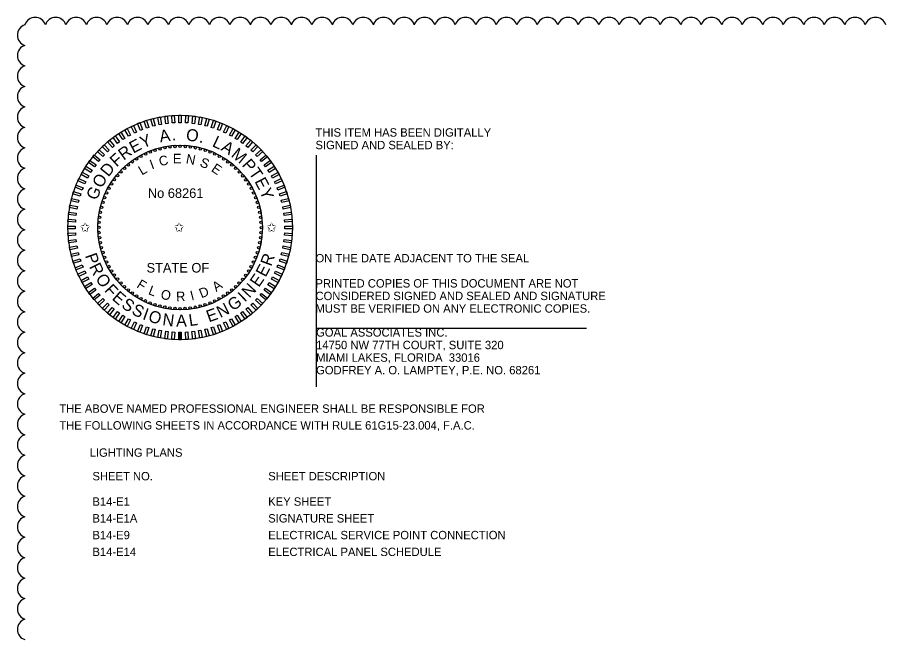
# Model space of a CAD drawing. Extents: x -811.3 to -795.2, y -2199.5 to -2188.9.
# Drawn here: x -810.85 to -803.6, y -2194.13 to -2188.94 of the extents above; entities that cross this region are included whole.
import ezdxf

# ---------------------------------------------------------------- set-up
doc = ezdxf.new("R2010")
doc.units = 0
for name, color, linetype in [('PlotBorder_dp', 7, 'Continuous'), ('ScratchEle_dp', 7, 'Continuous'), ('SheetBorder_dp', 7, 'Continuous'), ('SheetLines_dp', 7, 'Continuous'), ('TextMinor', 7, 'Continuous'), ('TextMisc', 7, 'Continuous')]:
    doc.layers.add(name, color=color, linetype=linetype)

msp = doc.modelspace()

# ---------------------------------------------------------------- linework, layer by layer
at = {"layer": 'PlotBorder_dp'}
for p, q in [((-809.5001, -2191.6301), (-809.5003, -2191.5676)), ((-809.4901, -2191.6301), (-809.4903, -2191.5676)), ((-809.4801, -2191.6301), (-809.4803, -2191.5676))]:
    msp.add_line(p, q, dxfattribs=at)
for points in [[(-809.7508, -2189.8572), (-809.77, -2189.8635), (-809.7893, -2189.8041), (-809.7701, -2189.7979)], [(-809.6979, -2189.8425), (-809.7174, -2189.8475), (-809.7329, -2189.7871), (-809.7134, -2189.782)], [(-809.6441, -2189.8312), (-809.6639, -2189.8349), (-809.6756, -2189.7736), (-809.6558, -2189.7698)], [(-809.5897, -2189.8232), (-809.6097, -2189.8257), (-809.6175, -2189.7638), (-809.5975, -2189.7612)], [(-809.5349, -2189.8187), (-809.555, -2189.8199), (-809.559, -2189.7576), (-809.5388, -2189.7563)], [(-809.4799, -2189.8176), (-809.5001, -2189.8176), (-809.5001, -2189.7551), (-809.4799, -2189.7551)], [(-809.425, -2189.8199), (-809.4452, -2189.8187), (-809.4412, -2189.7563), (-809.4211, -2189.7576)], [(-809.3703, -2189.8257), (-809.3904, -2189.8232), (-809.3825, -2189.7613), (-809.3625, -2189.7638)], [(-809.3162, -2189.835), (-809.336, -2189.8312), (-809.3243, -2189.7699), (-809.3045, -2189.7736)], [(-809.2626, -2189.8476), (-809.2822, -2189.8426), (-809.2667, -2189.7821), (-809.2471, -2189.7871)], [(-809.21, -2189.8635), (-809.2292, -2189.8573), (-809.2099, -2189.7979), (-809.1907, -2189.8042)], [(-809.9027, -2189.9209), (-809.9204, -2189.9306), (-809.9505, -2189.8759), (-809.9328, -2189.8662)], [(-809.8535, -2189.8965), (-809.8717, -2189.9051), (-809.8983, -2189.8486), (-809.8801, -2189.84)], [(-809.8028, -2189.8753), (-809.8215, -2189.8827), (-809.8445, -2189.8246), (-809.8258, -2189.8172)], [(-809.1585, -2189.8828), (-809.1773, -2189.8753), (-809.1543, -2189.8173), (-809.1355, -2189.8247)], [(-809.1083, -2189.9052), (-809.1266, -2189.8966), (-809.1, -2189.8401), (-809.0817, -2189.8487)], [(-809.0596, -2189.9307), (-809.0773, -2189.921), (-809.0473, -2189.8663), (-809.0296, -2189.876)], [(-809.9962, -2189.9787), (-810.0125, -2189.9906), (-810.0492, -2189.94), (-810.0329, -2189.9282)], [(-809.9504, -2189.9483), (-809.9674, -2189.9591), (-810.0009, -2189.9064), (-809.9838, -2189.8956)], [(-809.0127, -2189.9592), (-809.0297, -2189.9484), (-808.9962, -2189.8957), (-808.9792, -2189.9065)], [(-808.9676, -2189.9907), (-808.9839, -2189.9788), (-808.9472, -2189.9283), (-808.9308, -2189.9402)], [(-810.0817, -2190.0478), (-810.0964, -2190.0616), (-810.1392, -2190.0161), (-810.1244, -2190.0022)], [(-810.04, -2190.0119), (-810.0556, -2190.0247), (-810.0954, -2189.9766), (-810.0798, -2189.9638)], [(-808.9245, -2190.0249), (-808.9401, -2190.012), (-808.9003, -2189.9639), (-808.8847, -2189.9768)], [(-808.8837, -2190.0617), (-808.8984, -2190.0479), (-808.8557, -2190.0024), (-808.841, -2190.0162)], [(-810.1579, -2190.127), (-810.1707, -2190.1425), (-810.2188, -2190.1027), (-810.206, -2190.0872)], [(-810.121, -2190.0862), (-810.1348, -2190.1009), (-810.1804, -2190.0581), (-810.1665, -2190.0434)], [(-808.8453, -2190.101), (-808.8591, -2190.0863), (-808.8136, -2190.0436), (-808.7998, -2190.0583)], [(-808.8094, -2190.1427), (-808.8223, -2190.1271), (-808.7742, -2190.0873), (-808.7613, -2190.1029)], [(-810.192, -2190.17), (-810.2039, -2190.1864), (-810.2544, -2190.1497), (-810.2426, -2190.1333)], [(-808.7762, -2190.1865), (-808.7881, -2190.1702), (-808.7376, -2190.1335), (-808.7257, -2190.1498)], [(-810.252, -2190.2621), (-810.2617, -2190.2798), (-810.3164, -2190.2497), (-810.3067, -2190.232)], [(-810.2235, -2190.2151), (-810.2343, -2190.2322), (-810.287, -2190.1987), (-810.2762, -2190.1817)], [(-808.7459, -2190.2323), (-808.7567, -2190.2153), (-808.7039, -2190.1818), (-808.6931, -2190.1989)], [(-808.7184, -2190.28), (-808.7281, -2190.2623), (-808.6734, -2190.2322), (-808.6637, -2190.2499)], [(-810.2775, -2190.3108), (-810.2861, -2190.3291), (-810.3426, -2190.3025), (-810.334, -2190.2842)], [(-808.694, -2190.3292), (-808.7026, -2190.311), (-808.6461, -2190.2844), (-808.6375, -2190.3027)], [(-810.3, -2190.361), (-810.3074, -2190.3798), (-810.3654, -2190.3568), (-810.358, -2190.338)], [(-808.6728, -2190.3799), (-808.6802, -2190.3612), (-808.6222, -2190.3382), (-808.6147, -2190.357)], [(-810.3351, -2190.4651), (-810.3401, -2190.4847), (-810.4006, -2190.4691), (-810.3956, -2190.4496)], [(-810.3192, -2190.4125), (-810.3254, -2190.4317), (-810.3848, -2190.4124), (-810.3786, -2190.3932)], [(-808.6548, -2190.4319), (-808.661, -2190.4127), (-808.6016, -2190.3934), (-808.5954, -2190.4126)], [(-808.64, -2190.4849), (-808.6451, -2190.4653), (-808.5846, -2190.4498), (-808.5796, -2190.4693)], [(-810.3477, -2190.5186), (-810.3515, -2190.5385), (-810.4129, -2190.5268), (-810.4091, -2190.5069)], [(-808.6287, -2190.5386), (-808.6325, -2190.5188), (-808.5711, -2190.5071), (-808.5673, -2190.5269)], [(-810.357, -2190.5728), (-810.3595, -2190.5928), (-810.4215, -2190.585), (-810.4189, -2190.565)], [(-808.6207, -2190.593), (-808.6232, -2190.573), (-808.5613, -2190.5652), (-808.5588, -2190.5852)], [(-810.3628, -2190.6275), (-810.3641, -2190.6476), (-810.4264, -2190.6437), (-810.4251, -2190.6236)], [(-808.6162, -2190.6478), (-808.6174, -2190.6277), (-808.5551, -2190.6238), (-808.5539, -2190.6439)], [(-810.3652, -2190.6824), (-810.3652, -2190.7026), (-810.4276, -2190.7026), (-810.4276, -2190.6824)], [(-810.3641, -2190.7374), (-810.3628, -2190.7575), (-810.4251, -2190.7614), (-810.4264, -2190.7413)], [(-808.6175, -2190.7577), (-808.6162, -2190.7376), (-808.5539, -2190.7415), (-808.5551, -2190.7616)], [(-808.6151, -2190.7028), (-808.6151, -2190.6826), (-808.5527, -2190.6826), (-808.5527, -2190.7028)], [(-810.3595, -2190.7922), (-810.357, -2190.8122), (-810.4189, -2190.82), (-810.4215, -2190.8)], [(-808.6233, -2190.8124), (-808.6207, -2190.7923), (-808.5588, -2190.8002), (-808.5613, -2190.8202)], [(-810.3516, -2190.8466), (-810.3478, -2190.8664), (-810.4091, -2190.8781), (-810.4129, -2190.8583)], [(-808.6325, -2190.8666), (-808.6287, -2190.8467), (-808.5674, -2190.8584), (-808.5712, -2190.8783)], [(-810.3402, -2190.9003), (-810.3352, -2190.9199), (-810.3957, -2190.9354), (-810.4007, -2190.9159)], [(-810.3255, -2190.9533), (-810.3192, -2190.9725), (-810.3786, -2190.9918), (-810.3849, -2190.9726)], [(-808.6611, -2190.9727), (-808.6548, -2190.9535), (-808.5954, -2190.9728), (-808.6017, -2190.992)], [(-808.6451, -2190.9201), (-808.6401, -2190.9005), (-808.5796, -2190.916), (-808.5846, -2190.9356)], [(-810.3075, -2191.0052), (-810.3, -2191.024), (-810.3581, -2191.047), (-810.3655, -2191.0282)], [(-808.6803, -2191.0242), (-808.6729, -2191.0054), (-808.6148, -2191.0284), (-808.6222, -2191.0472)], [(-810.2862, -2191.0559), (-810.2776, -2191.0742), (-810.3341, -2191.1008), (-810.3427, -2191.0825)], [(-810.2618, -2191.1052), (-810.2521, -2191.1229), (-810.3068, -2191.153), (-810.3165, -2191.1353)], [(-808.7282, -2191.1231), (-808.7185, -2191.1054), (-808.6638, -2191.1355), (-808.6735, -2191.1532)], [(-808.7027, -2191.0744), (-808.6941, -2191.0561), (-808.6376, -2191.0827), (-808.6462, -2191.101)], [(-810.2344, -2191.1529), (-810.2236, -2191.1699), (-810.2763, -2191.2034), (-810.2871, -2191.1863)], [(-808.7568, -2191.1701), (-808.746, -2191.153), (-808.6932, -2191.1865), (-808.704, -2191.2035)], [(-810.204, -2191.1987), (-810.1922, -2191.215), (-810.2427, -2191.2517), (-810.2545, -2191.2354)], [(-810.1708, -2191.2425), (-810.158, -2191.2581), (-810.2061, -2191.2979), (-810.2189, -2191.2823)], [(-808.8224, -2191.2582), (-808.8095, -2191.2427), (-808.7614, -2191.2825), (-808.7743, -2191.298)], [(-808.7882, -2191.2152), (-808.7763, -2191.1988), (-808.7258, -2191.2355), (-808.7377, -2191.2519)], [(-810.135, -2191.2842), (-810.1211, -2191.2989), (-810.1667, -2191.3416), (-810.1805, -2191.3269)], [(-810.0965, -2191.3235), (-810.0818, -2191.3373), (-810.1246, -2191.3828), (-810.1393, -2191.369)], [(-808.8985, -2191.3374), (-808.8838, -2191.3236), (-808.8411, -2191.3691), (-808.8558, -2191.383)], [(-808.8592, -2191.299), (-808.8454, -2191.2843), (-808.7999, -2191.327), (-808.8137, -2191.3418)], [(-810.0557, -2191.3603), (-810.0402, -2191.3732), (-810.08, -2191.4213), (-810.0955, -2191.4084)], [(-810.0127, -2191.3945), (-809.9964, -2191.4064), (-810.0331, -2191.4569), (-810.0494, -2191.445)], [(-808.984, -2191.4065), (-808.9677, -2191.3946), (-808.931, -2191.4451), (-808.9473, -2191.457)], [(-808.9402, -2191.3733), (-808.9247, -2191.3604), (-808.8848, -2191.4086), (-808.9004, -2191.4214)], [(-809.9676, -2191.426), (-809.9505, -2191.4368), (-809.984, -2191.4895), (-810.001, -2191.4787)], [(-809.9206, -2191.4545), (-809.9029, -2191.4642), (-809.933, -2191.5189), (-809.9507, -2191.5092)], [(-809.0775, -2191.4643), (-809.0598, -2191.4546), (-809.0297, -2191.5093), (-809.0474, -2191.519)], [(-809.0299, -2191.4369), (-809.0128, -2191.4261), (-808.9794, -2191.4788), (-808.9964, -2191.4896)], [(-809.8719, -2191.48), (-809.8536, -2191.4886), (-809.8802, -2191.5451), (-809.8985, -2191.5365)], [(-809.8217, -2191.5024), (-809.8029, -2191.5099), (-809.8259, -2191.5679), (-809.8447, -2191.5605)], [(-809.7702, -2191.5217), (-809.751, -2191.5279), (-809.7703, -2191.5873), (-809.7895, -2191.581)], [(-809.7176, -2191.5376), (-809.698, -2191.5426), (-809.7136, -2191.6031), (-809.7331, -2191.5981)], [(-809.2824, -2191.5427), (-809.2628, -2191.5376), (-809.2473, -2191.5981), (-809.2668, -2191.6031)], [(-809.2294, -2191.5279), (-809.2102, -2191.5217), (-809.1909, -2191.5811), (-809.2101, -2191.5873)], [(-809.1775, -2191.5099), (-809.1587, -2191.5025), (-809.1357, -2191.5606), (-809.1545, -2191.568)], [(-809.1268, -2191.4887), (-809.1085, -2191.4801), (-809.0819, -2191.5366), (-809.1002, -2191.5452)], [(-809.6641, -2191.5502), (-809.6443, -2191.554), (-809.656, -2191.6153), (-809.6758, -2191.6116)], [(-809.6099, -2191.5594), (-809.5899, -2191.562), (-809.5977, -2191.6239), (-809.6177, -2191.6214)], [(-809.5552, -2191.5653), (-809.5351, -2191.5665), (-809.539, -2191.6288), (-809.5592, -2191.6276)], [(-809.5003, -2191.5676), (-809.4801, -2191.5676), (-809.4801, -2191.6301), (-809.5003, -2191.6301)], [(-809.4453, -2191.5665), (-809.4252, -2191.5653), (-809.4213, -2191.6276), (-809.4414, -2191.6289)], [(-809.3906, -2191.562), (-809.3705, -2191.5595), (-809.3627, -2191.6214), (-809.3827, -2191.624)], [(-809.3362, -2191.554), (-809.3163, -2191.5503), (-809.3046, -2191.6116), (-809.3245, -2191.6154)]]:
    msp.add_lwpolyline(points, close=True, dxfattribs=at)
for centre in [(-809.6165, -2190.027), (-809.5745, -2190.0204), (-809.5321, -2190.0164), (-809.4896, -2190.0151), (-809.447, -2190.0165), (-809.4047, -2190.0205), (-809.3626, -2190.0272), (-809.816, -2190.0987), (-809.7781, -2190.0794), (-809.739, -2190.0625), (-809.6989, -2190.0481), (-809.6581, -2190.0363), (-809.3211, -2190.0366), (-809.2802, -2190.0485), (-809.2402, -2190.0629), (-809.2012, -2190.0798), (-809.1633, -2190.0992), (-809.9215, -2190.1702), (-809.8879, -2190.1442), (-809.8527, -2190.1203), (-809.1266, -2190.1209), (-809.0915, -2190.1448), (-809.0579, -2190.171), (-809.9836, -2190.2284), (-809.9535, -2190.1984), (-809.026, -2190.1991), (-808.9959, -2190.2292), (-810.0379, -2190.2939), (-810.0118, -2190.2603), (-808.9678, -2190.2612), (-808.9417, -2190.2948), (-810.0835, -2190.3657), (-810.0618, -2190.3291), (-808.9178, -2190.3301), (-808.8962, -2190.3667), (-810.1198, -2190.4427), (-810.1029, -2190.4036), (-808.8769, -2190.4047), (-808.86, -2190.4437), (-810.1462, -2190.5236), (-810.1343, -2190.4827), (-808.8456, -2190.4838), (-808.8338, -2190.5247), (-810.1622, -2190.6071), (-810.1555, -2190.5651), (-808.8245, -2190.5662), (-808.8179, -2190.6082), (-810.1662, -2190.6495), (-808.814, -2190.6506), (-810.1676, -2190.692), (-810.1663, -2190.7346), (-808.814, -2190.7357), (-808.8127, -2190.6932), (-810.1623, -2190.7769), (-810.1557, -2190.819), (-808.8248, -2190.8201), (-808.8181, -2190.7781), (-810.1464, -2190.8605), (-810.1346, -2190.9014), (-808.846, -2190.9025), (-808.8341, -2190.8616), (-810.1202, -2190.9415), (-808.8604, -2190.9425), (-810.1034, -2190.9805), (-810.0841, -2191.0185), (-808.8967, -2191.0195), (-808.8774, -2190.9816), (-810.0624, -2191.0551), (-810.0385, -2191.0903), (-808.9424, -2191.0913), (-808.9184, -2191.0561), (-810.0125, -2191.124), (-809.9844, -2191.1559), (-809.9543, -2191.1861), (-809.0268, -2191.1868), (-808.9967, -2191.1568), (-808.9685, -2191.1249), (-809.9224, -2191.2142), (-809.8888, -2191.2403), (-809.8536, -2191.2643), (-809.1276, -2191.2649), (-809.0924, -2191.241), (-809.0587, -2191.215), (-809.817, -2191.286), (-809.7791, -2191.3053), (-809.74, -2191.3223), (-809.7, -2191.3367), (-809.2813, -2191.3371), (-809.2413, -2191.3227), (-809.2022, -2191.3058), (-809.1642, -2191.2865), (-809.6591, -2191.3486), (-809.6176, -2191.358), (-809.5756, -2191.3647), (-809.5332, -2191.3687), (-809.4901, -2191.3701), (-809.4481, -2191.3688), (-809.4058, -2191.3648), (-809.3637, -2191.3582), (-809.3222, -2191.3489)]:
    msp.add_circle(centre, 0.01, dxfattribs=at)
at = {"layer": 'ScratchEle_dp'}
for centre, start, end in [((-810.7588, -2189.0862), 107.5, 252.5), ((-810.7002, -2189.0276), 17.5, 162.5), ((-810.5291, -2189.0276), 17.5, 162.5), ((-810.358, -2189.0276), 17.5, 162.5), ((-810.1868, -2189.0276), 17.5, 162.5), ((-810.0157, -2189.0276), 17.5, 162.5), ((-809.8446, -2189.0276), 17.5, 162.5), ((-809.6735, -2189.0276), 17.5, 162.5), ((-809.5024, -2189.0276), 17.5, 162.5), ((-809.3312, -2189.0276), 17.5, 162.5), ((-809.1601, -2189.0276), 17.5, 162.5), ((-808.989, -2189.0276), 17.5, 162.5), ((-808.8179, -2189.0276), 17.5, 162.5), ((-808.6467, -2189.0276), 17.5, 162.5), ((-808.4756, -2189.0276), 17.5, 162.5), ((-808.3045, -2189.0276), 17.5, 162.5), ((-808.1334, -2189.0276), 17.5, 162.5), ((-807.9622, -2189.0276), 17.5, 162.5), ((-807.7911, -2189.0276), 17.5, 162.5), ((-807.62, -2189.0276), 17.5, 162.5), ((-807.4489, -2189.0276), 17.5, 162.5), ((-807.2778, -2189.0276), 17.5, 162.5), ((-807.1066, -2189.0276), 17.5, 162.5), ((-806.9355, -2189.0276), 17.5, 162.5), ((-806.7644, -2189.0276), 17.5, 162.5), ((-806.5933, -2189.0276), 17.5, 162.5), ((-806.4221, -2189.0276), 17.5, 162.5), ((-806.251, -2189.0276), 17.5, 162.5), ((-806.0799, -2189.0276), 17.5, 162.5), ((-805.9088, -2189.0276), 17.5, 162.5), ((-805.7377, -2189.0276), 17.5, 162.5), ((-805.5665, -2189.0276), 17.5, 162.5), ((-805.3954, -2189.0276), 17.5, 162.5), ((-805.2243, -2189.0276), 17.5, 162.5), ((-805.0532, -2189.0276), 17.5, 162.5), ((-804.882, -2189.0276), 17.5, 162.5), ((-804.7109, -2189.0276), 17.5, 162.5), ((-804.5398, -2189.0276), 17.5, 162.5), ((-804.3687, -2189.0276), 17.5, 162.5), ((-804.1976, -2189.0276), 17.5, 162.5), ((-804.0264, -2189.0276), 17.5, 162.5), ((-803.8553, -2189.0276), 17.5, 162.5), ((-803.6842, -2189.0276), 17.5, 162.5), ((-810.7588, -2189.2573), 107.5, 252.5), ((-810.7588, -2189.4284), 107.5, 252.5), ((-810.7588, -2189.5996), 107.5, 252.5), ((-810.7588, -2189.7707), 107.5, 252.5), ((-810.7588, -2189.9418), 107.5, 252.5), ((-810.7588, -2190.1129), 107.5, 252.5), ((-810.7588, -2190.2841), 107.5, 252.5), ((-810.7588, -2190.4552), 107.5, 252.5), ((-810.7588, -2190.6263), 107.5, 252.5), ((-810.7588, -2190.7974), 107.5, 252.5), ((-810.7588, -2190.9685), 107.5, 252.5), ((-810.7588, -2191.1397), 107.5, 252.5), ((-810.7588, -2191.3108), 107.5, 252.5), ((-810.7588, -2191.4819), 107.5, 252.5), ((-810.7588, -2191.653), 107.5, 252.5), ((-810.7588, -2191.8242), 107.5, 252.5), ((-810.7588, -2191.9953), 107.5, 252.5), ((-810.7588, -2192.1664), 107.5, 252.5), ((-810.7588, -2192.3375), 107.5, 252.5), ((-810.7588, -2192.5087), 107.5, 252.5), ((-810.7588, -2192.6798), 107.5, 252.5), ((-810.7588, -2192.8509), 107.5, 252.5), ((-810.7588, -2193.022), 107.5, 252.5), ((-810.7588, -2193.1931), 107.5, 252.5), ((-810.7588, -2193.3643), 107.5, 252.5), ((-810.7588, -2193.5354), 107.5, 252.5), ((-810.7588, -2193.7065), 107.5, 252.5), ((-810.7588, -2193.8776), 107.5, 252.5), ((-810.7588, -2194.0488), 107.5, 252.5)]:
    msp.add_arc(centre, 0.0897, start, end, dxfattribs=at)
at = {"layer": 'SheetLines_dp'}
for radius in [0.9375, 0.6875]:
    msp.add_circle((-809.4901, -2190.6926), radius, dxfattribs=at)
at = {"layer": 'TextMisc'}
for p, q in [((-808.3546, -2190.0892), (-808.3546, -2192.0239)), ((-808.3546, -2191.5339), (-806.0979, -2191.5339))]:
    msp.add_line(p, q, dxfattribs=at)

# ---------------------------------------------------------------- texts
at = {"layer": 'PlotBorder_dp'}
for s, height, rotation, p in [('A', 0.1, 8.80884, (-809.6551, -2189.982)), ('O', 0.1, 352.18771, (-809.4449, -2189.9645)), ('E', 0.1, 28.10553, (-809.8806, -2190.0764)), ('Y', 0.1, 21.06329, (-809.8021, -2190.0332)), ('.', 0.1, 1.04184, (-809.5575, -2189.9662)), ('L', 0.1, 334.67271, (-809.2279, -2190.0118)), ('R', 0.1, 35.92688, (-809.9609, -2190.1353)), ('.', 0.1, 343.52684, (-809.3358, -2189.9796)), ('A', 0.1, 328.40959, (-809.1552, -2190.0445)), ('F', 0.1, 42.37723, (-810.0205, -2190.1917)), ('C', 0.08, 12.20255, (-809.6579, -2190.181)), ('E', 0.08, 0.41861, (-809.5498, -2190.1575)), ('N', 0.08, 349.29143, (-809.4455, -2190.1561)), ('M', 0.1, 320.6426, (-809.0707, -2190.0957)), ('D', 0.1, 50.8569, (-810.0886, -2190.2754)), ('I', 0.08, 20.01168, (-809.7258, -2190.2085)), ('S', 0.08, 337.02207, (-809.3325, -2190.1778)), ('E', 0.08, 325.86633, (-809.2358, -2190.218)), ('P', 0.1, 311.19658, (-808.9784, -2190.1727)), ('L', 0.08, 30.40215, (-809.8093, -2190.259)), ('T', 0.1, 304.45632, (-808.9209, -2190.2363)), ('O', 0.1, 59.51777, (-810.1446, -2190.3702)), ('E', 0.1, 297.63152, (-808.8707, -2190.3072)), ('G', 0.1, 68.0518, (-810.1851, -2190.4709)), ('Y', 0.1, 290.58928, (-808.8281, -2190.386)), ('P', 0.1, 289.40551, (-810.2848, -2190.9272)), ('R', 0.1, 69.5134, (-808.7299, -2191.0223)), ('R', 0.1, 296.14576, (-810.2518, -2191.0188)), ('E', 0.1, 62.47116, (-808.7761, -2191.113)), ('O', 0.1, 303.96711, (-810.2003, -2191.1194)), ('E', 0.1, 55.42892, (-808.833, -2191.1974)), ('F', 0.1, 312.62798, (-810.1279, -2191.2215)), ('F', 0.08, 328.72408, (-809.8582, -2191.1892)), ('L', 0.08, 339.29159, (-809.7609, -2191.2483)), ('A', 0.08, 34.49917, (-809.1883, -2191.232)), ('N', 0.1, 47.17876, (-808.9123, -2191.2864)), ('E', 0.1, 319.07833, (-810.0645, -2191.2898)), ('O', 0.08, 349.68206, (-809.6562, -2191.288)), ('R', 0.08, 2.33977, (-809.5217, -2191.3099)), ('I', 0.08, 14.20366, (-809.3941, -2191.3032)), ('D', 0.08, 22.01279, (-809.312, -2191.2845)), ('I', 0.1, 43.64556, (-808.9499, -2191.3209)), ('S', 0.1, 326.12056, (-809.9869, -2191.3557)), ('N', 0.1, 26.86136, (-809.1544, -2191.4501)), ('G', 0.1, 35.11153, (-809.0492, -2191.3941)), ('S', 0.1, 333.193, (-809.9015, -2191.4119)), ('I', 0.1, 340.26543, (-809.8098, -2191.457)), ('O', 0.1, 343.79863, (-809.7621, -2191.4753)), ('E', 0.1, 19.81912, (-809.2498, -2191.4856)), ('N', 0.1, 352.45949, (-809.6411, -2191.5073)), ('A', 0.1, 0.70966, (-809.5227, -2191.5206)), ('L', 0.1, 8.47665, (-809.4105, -2191.5174))]:
    msp.add_text(s, height=height, rotation=rotation, dxfattribs=at).set_placement(p)
for s, p in [('No 68261', (-809.7591, -2190.4454)), ('✩', (-810.3251, -2190.7305)), ('✩', (-809.5404, -2190.7305)), ('✩', (-808.7685, -2190.7305)), ('STATE OF', (-809.7698, -2191.0688))]:
    msp.add_text(s, height=0.08, dxfattribs=at).set_placement(p)
at = {"layer": 'SheetBorder_dp'}
for s, p in [('THIS ITEM HAS BEEN DIGITALLY', (-808.3596, -2189.934)), ('SIGNED AND SEALED BY:', (-808.3596, -2190.039)), ('ON THE DATE ADJACENT TO THE SEAL', (-808.3596, -2190.984)), ('PRINTED COPIES OF THIS DOCUMENT ARE NOT ', (-808.3596, -2191.194)), ('CONSIDERED SIGNED AND SEALED AND SIGNATURE ', (-808.3596, -2191.299)), ('MUST BE VERIFIED ON ANY ELECTRONIC COPIES.', (-808.3596, -2191.404)), ('GOAL ASSOCIATES INC.', (-808.3546, -2191.6039)), ('14750 NW 77TH COURT, SUITE 320', (-808.3546, -2191.7089)), ('MIAMI LAKES, FLORIDA  33016', (-808.3546, -2191.8139)), ('GODFREY A. O. LAMPTEY, P.E. NO. 68261', (-808.3546, -2191.9189)), ('THE ABOVE NAMED PROFESSIONAL ENGINEER SHALL BE RESPONSIBLE FOR ', (-810.4987, -2192.24)), ('THE FOLLOWING SHEETS IN ACCORDANCE WITH RULE 61G15-23.004, F.A.C.', (-810.4987, -2192.38)), ('LIGHTING PLANS', (-810.245, -2192.6071))]:
    msp.add_text(s, height=0.07, dxfattribs=at).set_placement(p)
at = {"layer": 'TextMinor'}
for s, p in [('SHEET NO.', (-810.2215, -2192.8041)), ('SHEET DESCRIPTION', (-808.7542, -2192.8041)), ('B14-E1', (-810.2215, -2193.0162)), ('KEY SHEET', (-808.7542, -2193.0162)), ('B14-E1A', (-810.2215, -2193.1562)), ('SIGNATURE SHEET', (-808.7542, -2193.1562)), ('B14-E9', (-810.2215, -2193.2962)), ('ELECTRICAL SERVICE POINT CONNECTION', (-808.7542, -2193.2962)), ('B14-E14', (-810.2215, -2193.4362)), ('ELECTRICAL PANEL SCHEDULE', (-808.7542, -2193.4362))]:
    msp.add_text(s, height=0.07, dxfattribs=at).set_placement(p)

doc.saveas('drawing.dxf')
